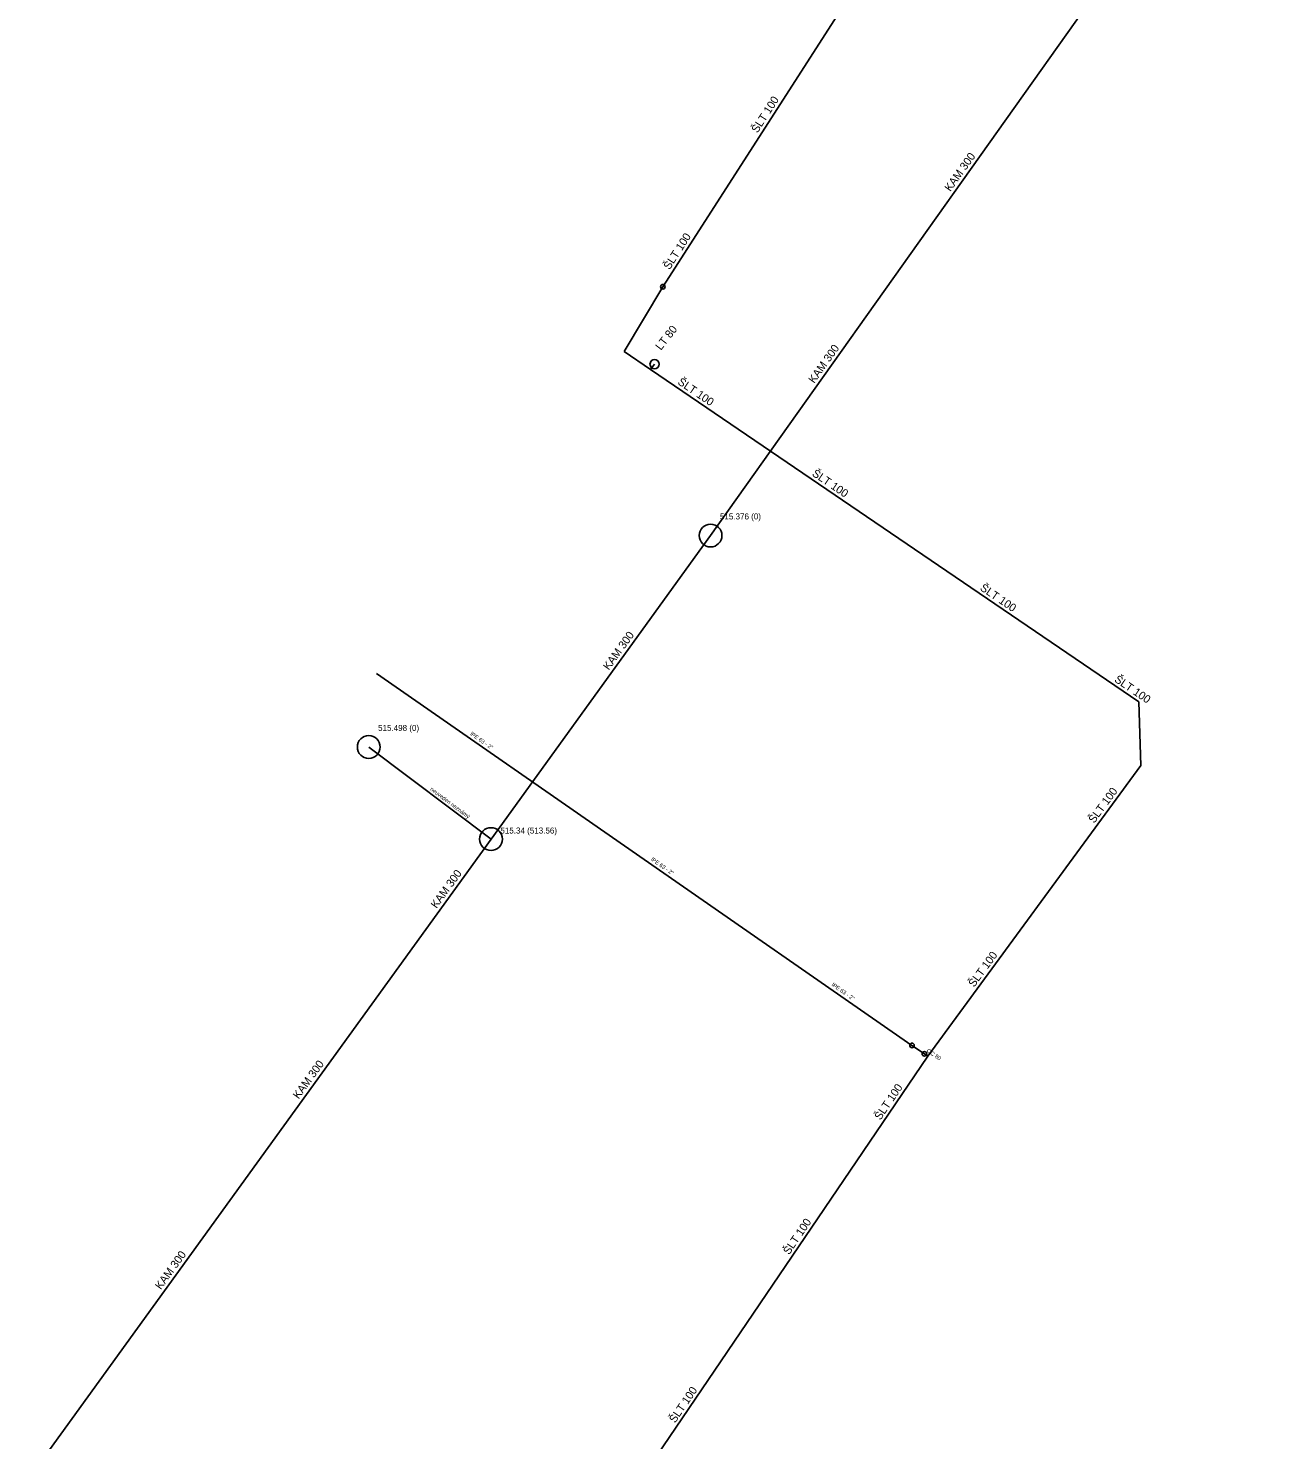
# Model space of a CAD drawing. Extents: x -668995 to -668929, y -1128059 to -1127935.
# Drawn here: x -668971.5 to -668943.89, y -1127997.4 to -1127966.43 of the extents above; entities that cross this region are included whole.
import ezdxf

# ---------------------------------------------------------------- set-up
doc = ezdxf.new("R2010")
doc.units = 0
for name, color, linetype in [('hydrant_o', 7, 'Continuous'), ('JEDN_D', 7, 'Continuous'), ('JEDN_O', 7, 'Continuous'), ('k_sachta_clip_Layer', 7, 'Continuous'), ('k_sachta_clip_LayerAnotace', 7, 'Continuous'), ('k_sachta_o', 7, 'Continuous'), ('kanal_clip_LayerAnotace', 7, 'Continuous'), ('soupe_o', 7, 'Continuous'), ('VOD_D', 7, 'Continuous'), ('VOD_O', 7, 'Continuous'), ('vodovod_clip_LayerAnotace', 7, 'Continuous')]:
    doc.layers.add(name, color=color, linetype=linetype)

msp = doc.modelspace()

# ---------------------------------------------------------------- linework, layer by layer
at = {"layer": 'hydrant_o'}
msp.add_circle((-668957.76, -1127973.8), 0.1, dxfattribs=at)
at = {"layer": 'JEDN_D'}
for p, q in [((-668956.53, -1127977.56), (-668943.89, -1127959.755)), ((-668961.347, -1127984.22), (-668956.53, -1127977.56)), ((-668971.5, -1127998.26), (-668961.347, -1127984.22))]:
    msp.add_line(p, q, dxfattribs=at)
at = {"layer": 'JEDN_O'}
msp.add_line((-668961.347, -1127984.22), (-668964.03, -1127982.2), dxfattribs=at)
at = {"layer": 'k_sachta_clip_Layer'}
for p, q in [((-668956.53, -1127977.56), (-668956.53, -1127977.56)), ((-668964.03, -1127982.2), (-668964.03, -1127982.2)), ((-668961.347, -1127984.22), (-668961.347, -1127984.22))]:
    msp.add_line(p, q, dxfattribs=at)
at = {"layer": 'k_sachta_o'}
for centre in [(-668956.53, -1127977.56), (-668964.03, -1127982.2), (-668961.347, -1127984.22)]:
    msp.add_circle(centre, 0.25, dxfattribs=at)
at = {"layer": 'soupe_o'}
for centre in [(-668957.578, -1127972.102), (-668952.112, -1127988.747), (-668951.839, -1127988.931)]:
    msp.add_circle(centre, 0.05, dxfattribs=at)
at = {"layer": 'VOD_D'}
msp.add_lwpolyline([(-668962.706, -1128005.131), (-668961.399, -1128003.191), (-668951.762, -1127988.985), (-668947.09, -1127982.604), (-668947.139, -1127981.212), (-668949.061, -1127979.903), (-668957.851, -1127973.916), (-668958.425, -1127973.525)], dxfattribs=at)
at = {"layer": 'VOD_O'}
for p, q in [((-668957.851, -1127973.916), (-668957.76, -1127973.8)), ((-668951.839, -1127988.931), (-668951.762, -1127988.985))]:
    msp.add_line(p, q, dxfattribs=at)
for points in [[(-668958.425, -1127973.525), (-668957.578, -1127972.102), (-668950.322, -1127960.812)], [(-668963.856, -1127980.589), (-668952.112, -1127988.747), (-668951.839, -1127988.931)]]:
    msp.add_lwpolyline(points, dxfattribs=at)

# ---------------------------------------------------------------- texts
at = {"layer": 'k_sachta_clip_LayerAnotace'}
for s, p in [('515.376 (0)', (-668956.325, -1127977.207)), ('515.498 (0)', (-668963.825, -1127981.847)), ('515.34 (513.56)', (-668961.142, -1127984.098))]:
    msp.add_text(s, height=0.13163, dxfattribs=at).set_placement(p)
at = {"layer": 'kanal_clip_LayerAnotace'}
for s, height, rotation, p in [('KAM 300', 0.1755, 54.6285, (-668951.269, -1127970.027)), ('KAM 300', 0.1755, 54.6289, (-668954.256, -1127974.235)), ('KAM 300', 0.1755, 54.1264, (-668958.763, -1127980.527)), ('neuveden neznámý', 0.08776, 323.0242, (-668962.692, -1127983.141)), ('KAM 300', 0.1755, 54.1257, (-668962.543, -1127985.754)), ('KAM 300', 0.1755, 54.1255, (-668965.567, -1127989.936)), ('KAM 300', 0.1755, 54.1256, (-668968.591, -1127994.117))]:
    msp.add_text(s, height=height, rotation=rotation, dxfattribs=at).set_placement(p)
at = {"layer": 'vodovod_clip_LayerAnotace'}
for s, height, rotation, p in [('ŠLT 100', 0.1755, 57.2713, (-668955.502, -1127968.741)), ('ŠLT 100', 0.1755, 57.2999, (-668957.43, -1127971.742)), ('LT 80', 0.1755, 51.777, (-668957.621, -1127973.509)), ('ŠLT 100', 0.1755, 325.7403, (-668957.267, -1127974.228)), ('ŠLT 100', 0.1755, 325.7403, (-668954.319, -1127976.236)), ('ŠLT 100', 0.1755, 325.7399, (-668950.634, -1127978.746)), ('ŠLT 100', 0.1755, 325.7399, (-668947.686, -1127980.754)), ('lPE 63 - 2"', 0.08776, 325.2325, (-668961.814, -1127981.932)), ('ŠLT 100', 0.1755, 53.7914, (-668948.116, -1127983.886)), ('lPE 63 - 2"', 0.08776, 325.2323, (-668957.848, -1127984.685)), ('ŠLT 100', 0.1755, 53.7907, (-668950.75, -1127987.483)), ('lPE 63 - 2"', 0.08776, 325.2326, (-668953.883, -1127987.437)), ('OC 80', 0.0878, 325.3115, (-668951.801, -1127988.882)), ('ŠLT 100', 0.1755, 55.8689, (-668952.806, -1127990.4)), ('ŠLT 100', 0.1755, 55.8692, (-668954.808, -1127993.353)), ('ŠLT 100', 0.1755, 55.869, (-668957.31, -1127997.044))]:
    msp.add_text(s, height=height, rotation=rotation, dxfattribs=at).set_placement(p)

doc.saveas('drawing.dxf')
